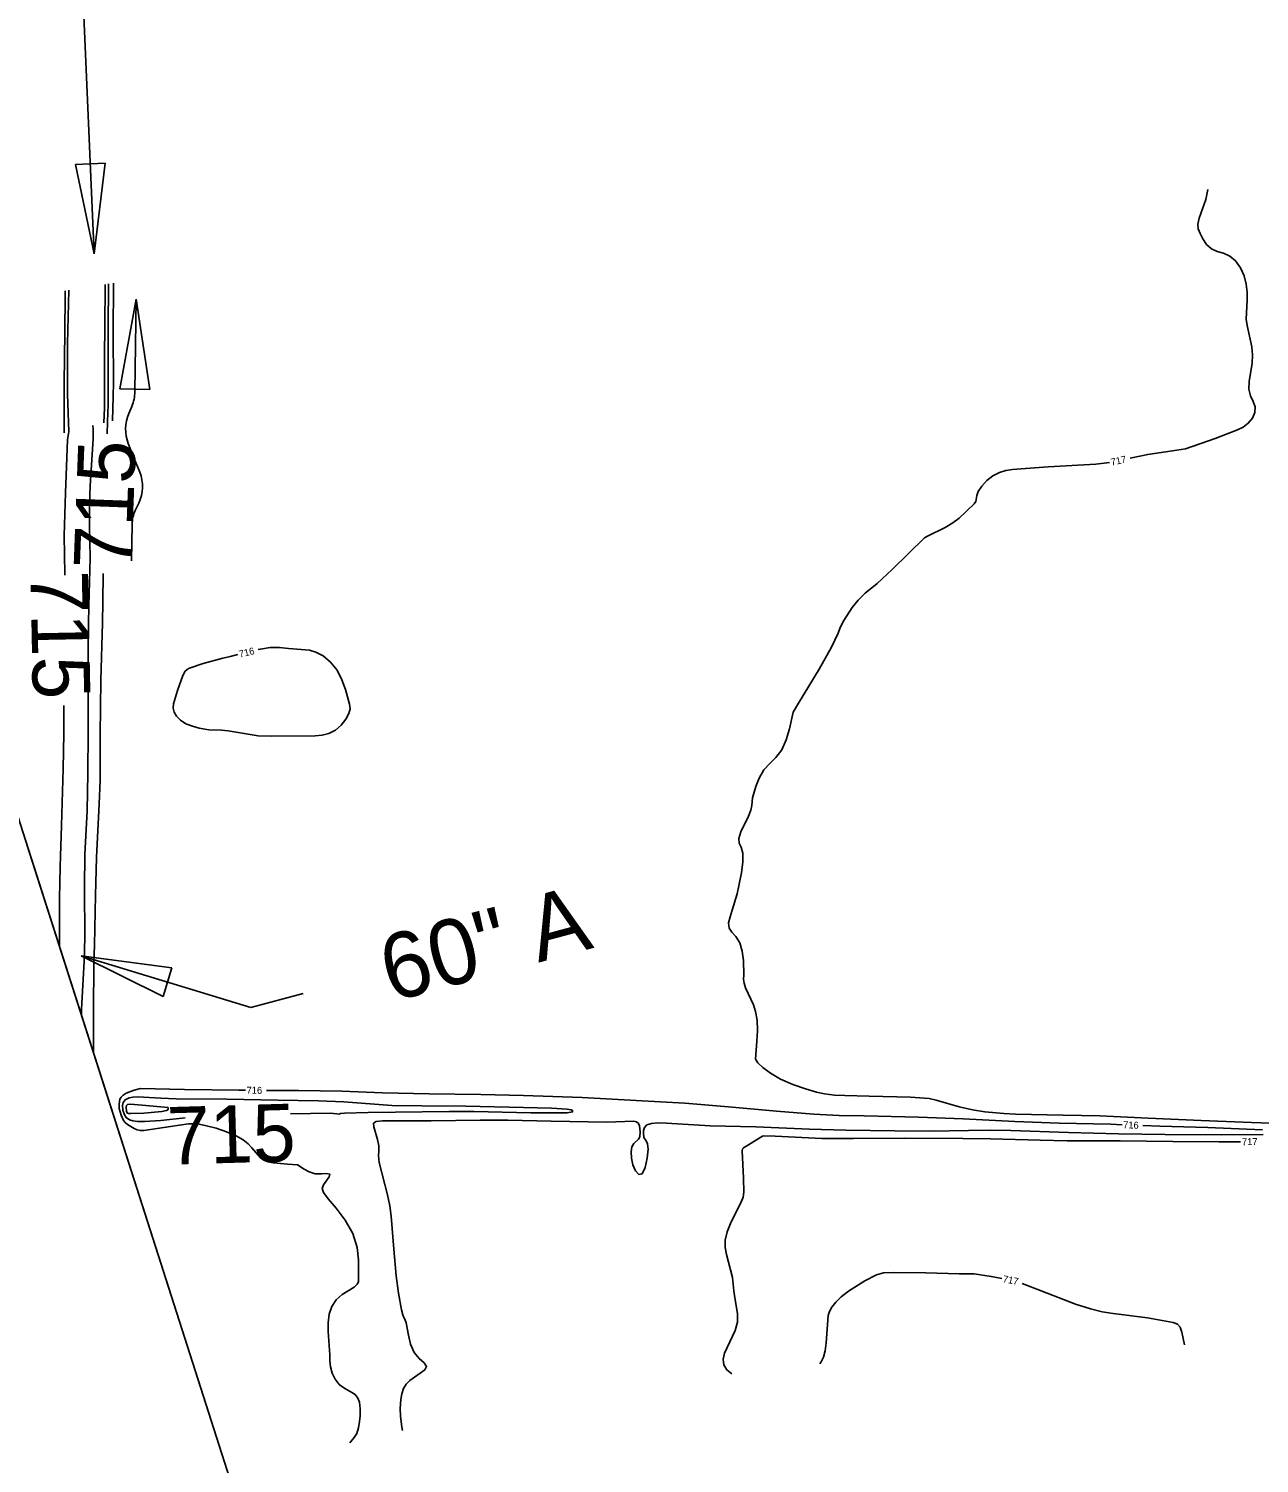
# Model space of a CAD drawing. Extents: x -361782338 to 28259792, y -263199453 to 8342113.
# Drawn here: x 1400786 to 1401491, y 576244 to 577066 of the extents above; entities that cross this region are included whole.
import ezdxf

# ---------------------------------------------------------------- set-up
doc = ezdxf.new("R2010")
doc.units = 0
for name, color, linetype in [('DT_X_Contour_Minor', 7, 'Continuous'), ('DT_X_Terrain_Ground_Line', 7, 'Continuous'), ('Level 19', 7, 'Continuous'), ('Level 31', 7, 'Continuous'), ('Level 40', 7, 'Continuous'), ('SC_Scratch1', 7, 'Continuous')]:
    doc.layers.add(name, color=color, linetype=linetype)

msp = doc.modelspace()

# ---------------------------------------------------------------- linework, layer by layer
at = {"layer": 'DT_X_Contour_Minor'}
for points in [[(1401461.8, 576974), (1401460.68, 576968.33), (1401456.95, 576957.61), (1401456.19, 576954.13), (1401456.41, 576951.48), (1401457.41, 576948.88), (1401459.02, 576945.77), (1401461.21, 576942.61), (1401463.99, 576940.08), (1401467.31, 576938.6), (1401470.93, 576937.52), (1401474.52, 576935.91), (1401477.8, 576933.07), (1401480.57, 576929.18), (1401482.63, 576924.65), (1401483.84, 576919.87), (1401484.36, 576915.13), (1401484.36, 576912.52)], [(1400830.1, 576919.66), (1400829.8, 576895.23), (1400829.59, 576879.4), (1400829.74, 576849.02), (1400829.35, 576840.34)], [(1400831.99, 576919.97), (1400831.77, 576894.55), (1400831.72, 576879.72), (1400831.75, 576850.78), (1400831.46, 576840.86)], [(1400834.83, 576920.43), (1400834.65, 576891.28), (1400834.71, 576863.47), (1400834.63, 576855.48), (1400834.31, 576841.54)], [(1400806.46, 576834.7), (1400806.54, 576863.16), (1400806.84, 576892.23), (1400807.2, 576913.11), (1400807.09, 576915.95)], [(1400809.13, 576835.37), (1400808.46, 576856.62), (1400808.47, 576885.76), (1400809.3, 576916.31)], [(1401484.36, 576912.52), (1401484.39, 576910.71), (1401483.93, 576899.72), (1401484.47, 576896.06), (1401487.09, 576883.87), (1401487.52, 576879.31), (1401487.33, 576874.43), (1401485.55, 576864.15), (1401485.37, 576859.56), (1401486.4, 576855.81), (1401487.95, 576852.61), (1401489.02, 576849.51), (1401488.82, 576846.21), (1401487.41, 576842.95), (1401485.08, 576840.1), (1401482.1, 576837.9), (1401478.85, 576836.28), (1401466.13, 576831.43), (1401449.14, 576825.44), (1401444.07, 576824.67), (1401427.48, 576822.3), (1401417.34, 576820.11)], [(1400816.38, 576501.06), (1400816.45, 576504.24), (1400818.07, 576532.01), (1400818.43, 576545.53), (1400818.16, 576574.13), (1400818.46, 576592.96), (1400819.67, 576618.02), (1400820.08, 576639.57), (1400820.31, 576662.9), (1400820.38, 576692.45), (1400820.2, 576714.02), (1400820.6, 576735.63), (1400820.99, 576749.34), (1400821.39, 576762.94), (1400821.08, 576781.39), (1400821.06, 576793.66), (1400821.47, 576804.33), (1400823.09, 576831.18), (1400823.11, 576836.54), (1400822.91, 576838.78)], [(1400831.21, 576834.11), (1400831.41, 576840.84)], [(1400809.13, 576835.37), (1400808.47, 576830.68), (1400807.28, 576800.26), (1400806.53, 576775.8)], [(1401405.59, 576817.7), (1401397.67, 576816.59), (1401370.44, 576815.05), (1401357.44, 576814.14), (1401349.92, 576813.64), (1401346.18, 576813.02), (1401342.44, 576811.87), (1401338.77, 576809.97), (1401335.3, 576807.23), (1401332.35, 576804.07), (1401330.33, 576801.07), (1401329.46, 576798.65), (1401328.92, 576795.23), (1401328.01, 576793.85), (1401319.31, 576785.75), (1401315.7, 576783), (1401311.33, 576780.34), (1401301.32, 576775.33), (1401299.61, 576774.38), (1401281.01, 576756.36), (1401272.37, 576748.3), (1401265.46, 576742.73), (1401261.48, 576738.82), (1401258.02, 576734.54), (1401253.33, 576727.18), (1401251.26, 576723.07), (1401250.03, 576719.77), (1401246.21, 576711.88), (1401239.16, 576699.14), (1401227.38, 576679.77), (1401224.29, 576674.62), (1401222.15, 576665.13), (1401220.28, 576658.83), (1401217.69, 576652.97), (1401214.43, 576648.64), (1401210.88, 576645.19), (1401207.55, 576641.5), (1401204.83, 576636.85), (1401202.82, 576631.95), (1401200.97, 576625.45), (1401200.6, 576621.07), (1401199.94, 576618.49), (1401198.59, 576615), (1401194.36, 576606.12), (1401193.12, 576602.27), (1401193.37, 576599.58), (1401194.45, 576597.19), (1401195.37, 576593.88), (1401195.37, 576588.82), (1401194.59, 576582.62), (1401192.1, 576570.59), (1401189.4, 576561.2), (1401188.09, 576557.26), (1401187.28, 576553.82), (1401187.51, 576550.93), (1401189.09, 576548.52), (1401191.41, 576545.97), (1401193.63, 576542.51), (1401195.09, 576537.7), (1401195.83, 576532.33), (1401195.94, 576524.08), (1401195.86, 576521.59), (1401196.15, 576519.34), (1401197.04, 576516.73), (1401201.49, 576507), (1401202.77, 576503), (1401203.57, 576498.11), (1401203.76, 576492.21), (1401203.48, 576486.18), (1401202.7, 576475.71), (1401203.97, 576473.65), (1401206.8, 576470.92), (1401211.2, 576467.69), (1401217.05, 576464.36), (1401224.07, 576461.31), (1401231.32, 576458.76), (1401237.65, 576456.91), (1401242.25, 576455.87), (1401247.91, 576455.25), (1401253.86, 576454.9), (1401267.92, 576454.57), (1401291.46, 576454.04), (1401302.13, 576453.19), (1401306.31, 576452.27), (1401319.48, 576448.56), (1401327.04, 576446.74), (1401334.15, 576445.55), (1401344.99, 576444.58), (1401351.73, 576444.29), (1401379.06, 576443.79), (1401399.91, 576443.34), (1401427.73, 576442), (1401458.09, 576440.68), (1401486.93, 576439.5), (1401519.72, 576438.32)], [(1400806.53, 576775.8), (1400806.96, 576753.63), (1400806.96, 576753.1)], [(1400823.37, 576479.24), (1400823.38, 576502.82), (1400823.54, 576531.05), (1400823.87, 576541.14), (1400824.58, 576569.83), (1400825.1, 576591.34), (1400826.58, 576622.01), (1400827.1, 576635.38), (1400827.24, 576661.61), (1400827.55, 576692.89), (1400828.44, 576725.85), (1400828.64, 576737.89), (1400828.94, 576754.06)], [(1400906.14, 576707.57), (1400901.66, 576706.46), (1400897.49, 576705.56), (1400886.12, 576702.4), (1400877.86, 576699.52), (1400875.95, 576698.02), (1400874.53, 576695.55), (1400871.41, 576687.01), (1400869.23, 576679.38), (1400869.02, 576676.87), (1400869.56, 576674.63), (1400870.94, 576672.28), (1400873.18, 576669.96), (1400876.29, 576667.95), (1400880.12, 576666.48), (1400883.98, 576665.5), (1400889.48, 576664.48), (1400896.73, 576664.3), (1400900.6, 576663.88), (1400917.61, 576661.06), (1400925.54, 576660.88), (1400950.3, 576661.12), (1400954.29, 576661.5), (1400958.27, 576662.4), (1400962.03, 576664.19), (1400965.35, 576667.06), (1400967.98, 576670.48), (1400969.7, 576673.76), (1400970.34, 576676.48), (1400970.07, 576679.17), (1400967.75, 576687.5), (1400965.74, 576693.09), (1400962.93, 576698.57), (1400959.22, 576703.23), (1400955.01, 576706.77), (1400950.83, 576709.04), (1400947.04, 576710.02), (1400935.03, 576710.98), (1400930.01, 576711.58), (1400924.59, 576711.63), (1400918.95, 576710.75), (1400917.79, 576710.46)], [(1400806.32, 576678.34), (1400806.33, 576662.34), (1400806.05, 576642.04), (1400804.95, 576609.72), (1400804.15, 576586.17), (1400803.77, 576567.57), (1400803.84, 576540.22)], [(1400910.4, 576457.98), (1400906.63, 576457.99), (1400875.44, 576458.35), (1400850.28, 576458.98), (1400846.7, 576458.09), (1400842.07, 576456.29), (1400840.36, 576455.24), (1400839.18, 576454.1), (1400838.46, 576452.8), (1400837.96, 576449.93), (1400838.05, 576447.48), (1400839.16, 576443.78), (1400840.56, 576440.73), (1400841.53, 576439.48), (1400842.88, 576438.29), (1400846.62, 576436.06), (1400848.45, 576435.29), (1400850.03, 576434.92), (1400852.11, 576434.97), (1400867.45, 576437.24), (1400877.8, 576438.71), (1400881.04, 576438.75), (1400883.92, 576438.47), (1400888.07, 576437.68), (1400893.58, 576436.19), (1400899.59, 576434.18), (1400905.06, 576431.91), (1400909.16, 576429.6), (1400912.05, 576427.32), (1400914.15, 576425.06), (1400918.95, 576419.17), (1400920.86, 576417.89), (1400923.29, 576416.97), (1400926.47, 576416.32), (1400934.5, 576415.59), (1400940.29, 576415.29), (1400944.02, 576412.7), (1400946.95, 576411.15), (1400950.42, 576410.13), (1400954.06, 576410.03), (1400957.12, 576410.25), (1400958.71, 576409.9), (1400958.31, 576408.37), (1400955.09, 576403.72), (1400954.42, 576401.69), (1400955.22, 576399.36), (1400957.86, 576395.84), (1400962.39, 576390.47), (1400967.61, 576383.62), (1400971.99, 576375.9), (1400974.39, 576367.98), (1400975.22, 576360.76), (1400975.26, 576349.31), (1400975.12, 576348.2), (1400974.42, 576346.82), (1400972.68, 576345.19), (1400965.9, 576340.95), (1400962.43, 576337.94), (1400959.94, 576334.11), (1400958.43, 576329.63), (1400957.79, 576324.73), (1400957.81, 576319.67), (1400958.68, 576306.39), (1400958.76, 576302.94), (1400959.14, 576299.52), (1400960.11, 576295.9), (1400961.78, 576292.39), (1400964.19, 576289.39), (1400967.28, 576287.17), (1400970.51, 576285.42), (1400973.2, 576283.64), (1400974.86, 576281.49), (1400975.68, 576279.19), (1400976.2, 576275.45), (1400976.12, 576271.49), (1400975.81, 576268.25), (1400975.2, 576264.59), (1400974.16, 576261.32), (1400972.67, 576259.01), (1400970.22, 576256.07)], [(1400936.3, 576444.4), (1400959.22, 576444.89), (1400964.47, 576444.31), (1400964.68, 576444.62), (1400967.15, 576444.94), (1400980.74, 576445.31), (1400996.32, 576445.35), (1401027.2, 576445.86), (1401041.21, 576445.83), (1401073.97, 576445.09), (1401085.83, 576444.97), (1401094.75, 576445.09), (1401097.87, 576445.6), (1401097.89, 576446.33), (1401097.06, 576446.7), (1401094.77, 576447.05), (1401085.74, 576447.62), (1401069.76, 576448.14), (1401036.75, 576448.81), (1401011.52, 576449.06), (1400994.3, 576449.32), (1400966.81, 576451.28), (1400952.36, 576451.95), (1400928.95, 576452.34), (1400899.7, 576452.94), (1400870.71, 576452.97), (1400861.88, 576453.36), (1400848.77, 576454.18), (1400845.86, 576454), (1400843.85, 576453.58), (1400841.45, 576452.42), (1400840.34, 576450.99), (1400840.05, 576449.28), (1400840.2, 576446.65), (1400841.11, 576443.87), (1400842.12, 576442.31), (1400844.03, 576440.94), (1400845.8, 576440.36), (1400848.57, 576440.03), (1400852.52, 576440.01), (1400861.99, 576440.69), (1400875.95, 576442.25)], [(1400866.19, 576448.03), (1400844.67, 576449.95), (1400842.82, 576449.76), (1400842.23, 576449.18), (1400842.14, 576448.21), (1400842.31, 576445.86), (1400842.92, 576444.94), (1400843.35, 576444.75), (1400844.62, 576444.64), (1400852.28, 576444.94), (1400862.49, 576445.87), (1400865.09, 576446.41), (1400866.05, 576446.93), (1400866.19, 576448.03)], [(1401412.73, 576438.24), (1401406.37, 576438.46), (1401376.7, 576439.19), (1401351.25, 576440.12), (1401321.76, 576441.54), (1401296.18, 576442.58), (1401264.92, 576443.23), (1401250.64, 576443.55), (1401236.12, 576444.29), (1401214.79, 576446.02), (1401187.29, 576448.42), (1401162.12, 576450.5), (1401134.33, 576452.08), (1401103.35, 576453.79), (1401069.82, 576455.06), (1401045.25, 576455.54), (1401015.65, 576455.95), (1400988.92, 576456.5), (1400965.71, 576457.38), (1400940.83, 576457.83), (1400922.4, 576457.92)], [(1401000.47, 576262.99), (1400999.98, 576264.89), (1400999.31, 576271.32), (1400999.12, 576275.67), (1400999.41, 576280.85), (1400999.94, 576284.1), (1401000.92, 576287.16), (1401002.48, 576289.66), (1401004.64, 576291.75), (1401013.18, 576297.77), (1401014.17, 576299.79), (1401012.81, 576301.79), (1401010.01, 576304.23), (1401007.08, 576307.7), (1401005.05, 576312.47), (1401003.85, 576317.63), (1401002.6, 576324.71), (1401001.67, 576326.92), (1401001.15, 576327.81), (1401000.53, 576329.37), (1400999.8, 576332.15), (1400998.09, 576341.71), (1400996.79, 576351.69), (1400995.54, 576366.97), (1400993.91, 576385.81), (1400993.07, 576391.77), (1400991.79, 576398.02), (1400986.95, 576416.65), (1400986.71, 576420.4), (1400986.93, 576423.19), (1400986.89, 576426.06), (1400986.07, 576429.72), (1400983.89, 576436.95), (1400983.8, 576439.04), (1400985.25, 576440.07), (1400988.94, 576440.46), (1401002.34, 576440.48), (1401016.85, 576440.36), (1401045.01, 576440.9), (1401060.82, 576440.78), (1401085.64, 576440.24), (1401117.55, 576439.75), (1401132.89, 576440.28), (1401134.54, 576439.81), (1401135.63, 576438.92), (1401136.23, 576437.56), (1401136.59, 576434.22), (1401136.37, 576431.24), (1401135.7, 576430), (1401133.04, 576427.49), (1401131.88, 576425.5), (1401131.37, 576422.6), (1401131.57, 576419.08), (1401132.47, 576415.31), (1401134, 576411.83), (1401135.9, 576409.71), (1401137.83, 576410.13), (1401139.51, 576413.77), (1401140.69, 576419.12), (1401141.16, 576424.16), (1401140.81, 576427.33), (1401139.99, 576428.98), (1401138.66, 576430.84), (1401138.44, 576433.33), (1401138.54, 576435), (1401139.08, 576436.7), (1401140.47, 576438.1), (1401143.02, 576438.93), (1401146.79, 576439.25), (1401151.71, 576439.15), (1401176.64, 576437.59), (1401202.89, 576436.99), (1401233.58, 576435.67), (1401254.53, 576435.11), (1401282.49, 576434.75), (1401302.79, 576434.51), (1401324.66, 576434.98), (1401337.08, 576435.17), (1401348.94, 576434.87), (1401382.05, 576433.75), (1401410.71, 576433.06), (1401437.45, 576432.55), (1401469.54, 576432.36), (1401493.6, 576432.61)], [(1401493.27, 576435.31), (1401461.98, 576436.59), (1401434.31, 576437.49), (1401424.73, 576437.82)], [(1401480.7, 576428.49), (1401468.23, 576428.39), (1401441.88, 576428.55), (1401411.61, 576428.95), (1401381.27, 576429.09), (1401365.82, 576429.39), (1401337.29, 576430.13), (1401321.58, 576430.27), (1401287.98, 576430.45), (1401258.83, 576430.3), (1401240.68, 576430.31), (1401214.04, 576431.66), (1401207.5, 576431.92), (1401206.69, 576431.64), (1401203.32, 576429.59), (1401198.77, 576426.63), (1401195.85, 576425.08), (1401195.19, 576424.36), (1401195, 576423.21), (1401195.86, 576407.55), (1401196.08, 576399.5), (1401195.64, 576396.79), (1401194.27, 576393.39), (1401188.8, 576382.54), (1401186.38, 576376.83), (1401185.24, 576372.06), (1401185.24, 576367.94), (1401186.03, 576363.92), (1401189.6, 576350.75), (1401190.36, 576343.06), (1401190.8, 576339.11), (1401192.4, 576329.98), (1401192.36, 576325.13), (1401191.06, 576320.36), (1401184.97, 576307.44), (1401184.12, 576303.83), (1401184.52, 576300.6), (1401186.35, 576297.79), (1401189.08, 576295.52)], [(1401239.65, 576301.31), (1401240.35, 576302.29), (1401241.65, 576305.09), (1401242.59, 576308.7), (1401243.17, 576313.36), (1401244.27, 576328.93), (1401245.08, 576331.25), (1401246.46, 576333.78), (1401248.64, 576336.58), (1401251.83, 576339.66), (1401256.07, 576342.92), (1401265.33, 576348.82), (1401271.97, 576352.19), (1401276.07, 576353.42), (1401281.55, 576353.58), (1401300.23, 576353.35), (1401319.34, 576352.72), (1401327.99, 576352.88), (1401337.78, 576351.36), (1401343.84, 576350.17)], [(1401355.49, 576347.21), (1401366.46, 576343.08), (1401386.1, 576335.43), (1401394.7, 576332.74), (1401401.39, 576331.02), (1401407.68, 576330.07), (1401427.28, 576327.65), (1401442.04, 576324.91), (1401444.58, 576323.87), (1401446.07, 576322.21), (1401447.06, 576319.39), (1401448.51, 576312.07)]]:
    msp.add_lwpolyline(points, dxfattribs=at)
at = {"layer": 'DT_X_Terrain_Ground_Line'}
msp.add_line((1401030.77, 575831.77), (1400785.07, 576598.82), dxfattribs=at)
at = {"layer": 'Level 31'}
for p, q in [((1400838.48, 576859.74), (1400847.77, 576911.19)), ((1400847.06, 576858.25), (1400847.77, 576911.19)), ((1400847.77, 576911.19), (1400855.65, 576859.51)), ((1400855.65, 576859.51), (1400838.48, 576859.74)), ((1400845.27, 576849.72), (1400843.52, 576845.64)), ((1400843.29, 576828.54), (1400846.72, 576819.87)), ((1400846.72, 576819.87), (1400849.82, 576812.18)), ((1400849.28, 576794.26), (1400847.3, 576790.06)), ((1400845.19, 576761.21), (1400845.47, 576782.14))]:
    msp.add_line(p, q, dxfattribs=at)
for centre, radius, start, end in [((1400824.67, 576858.54), 22.4, 336.87127, 359.23129), ((1400864.11, 576836.82), 22.4, 156.83244, 201.6763), ((1400829.02, 576803.85), 22.4, 334.69861, 21.80707), ((1400864.66, 576781.89), 19.2, 154.74848, 179.23129)]:
    msp.add_arc(centre, radius, start, end, dxfattribs=at)
at = {"layer": 'Level 40'}
for p, q in [((1400812.95, 576988.31), (1400830.12, 576989.07)), ((1400823.76, 576937.15), (1400812.95, 576988.31)), ((1400830.12, 576989.07), (1400823.76, 576937.15)), ((1400913.49, 576505.46), (1400816.37, 576534.91)), ((1400863.23, 576511.71), (1400816.37, 576534.91)), ((1400816.37, 576534.91), (1400868.21, 576528.15)), ((1400868.21, 576528.15), (1400863.23, 576511.71)), ((1400913.49, 576505.46), (1400943.46, 576513.49))]:
    msp.add_line(p, q, dxfattribs=at)
msp.add_lwpolyline([(1400823.76, 576937.16), (1400799.45, 577496.21), (1400868.03, 577514.58)], dxfattribs=at)
at = {"layer": 'SC_Scratch1'}
msp.add_lwpolyline([(1400540.45, 577362.46), (1401030.77, 575831.77), (1401384.55, 574706.55), (1408690.57, 576642.83), (1409300.15, 577585.43), (1408847.28, 578980.35), (1403882.9, 579488.01), (1400534.4, 577997.59)], close=True, dxfattribs=at)

# ---------------------------------------------------------------- texts
at = {"layer": 'Level 19'}
for s, height, rotation, p in [('715', 33, 87.87454, (1400844.91, 576756.09)), ('717', 4, 12.19827, (1401406.76, 576815.78)), ('715', 33, 271.1179, (1400787.19, 576755.37)), ('716', 4, 13.9286, (1400907.25, 576705.79)), ('716', 4, 359.72009, (1400911.04, 576455.97)), ('715', 33, 1.63866, (1400865.93, 576415.3)), ('716', 4, 358.01841, (1401413.31, 576436.22)), ('717', 4, 0.43545, (1401481.46, 576426.49)), ('717', 4, 348.874, (1401344.18, 576348.07))]:
    msp.add_text(s, height=height, rotation=rotation, dxfattribs=at).set_placement(p)
at = {"layer": 'Level 40'}
msp.add_text('60" A', height=37.5, rotation=15, dxfattribs=at).set_placement((1400993.73, 576508.39))

doc.saveas('drawing.dxf')
